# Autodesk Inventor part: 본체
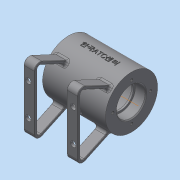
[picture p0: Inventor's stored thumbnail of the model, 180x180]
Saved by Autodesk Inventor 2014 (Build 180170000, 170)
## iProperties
Created: 2021-12
Part Number: 본체
Material: 일반
Document SubType Name: Modeling
Designer: dg
Density: 1 g/cm^3
Appearance: 기본값
Author: dg
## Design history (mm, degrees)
sketch "스케치1"
  geometry: L1 (0, 0)-(70, 0); L2 (0, 16)-(0, 29); L3 (0, 16)-(12, 16); L4 (12, 16)-(12, 14); L5 (12, 14)-(14, 14); L6 (14, 14)-(14, 21); L7 (14, 21)-(56, 21); L8 (56, 21)-(56, 14); L9 (56, 14)-(58, 14); L10 (58, 14)-(58, 16); L11 (58, 16)-(70, 16); L12 (70, 16)-(70, 29); L13 (0, 29)-(70, 29)
  constraints: 26 end point, 6 perpendicular, 5 parallel, 1 horizontal, 1 vertical alignment
  dimensions: "d0" = 70 distance of L1.start L1.end; "d1" = 32 diameter of L2.start L1; "d2" = 12 distance of L2.start L3.end; "d3" = 2 distance of L3.end L4.end; "d4" = 2 distance of L4.end L5.end; "d5" = 42 diameter of L6.end L1; "d6" = 42 distance of L6.end L7.end; "d7" = 2 distance of L8.end L9.end; "d8" = 2 distance of L9.end L10.end; "d9" = 12 distance of L10.end L11.end; "d10" = 32 diameter of L11 L1; "d11" = 58 diameter of L12.end L1; "d12" = 58 diameter of L2.end L1
revolve "회전1" sketch "스케치1" stored, may be unused: angle "d13" = 90 deg
node "작업축1"
fillet "모깎기1" dims "d14" = 3
fillet "모깎기2" dims "d15" = 0.3
node "작업 평면1"
sketch "스케치2"
  geometry: L1 (-55, 40)-(-55, -40); L2 (-55, 40)-(-17.993, 22.743); L3 (-55, -40)-(-17.993, -22.743); L4 (-20.438, -20.574)-(-52, -35.291); L5 (-52, -35.291)-(-52, 35.291); L6 (-52, 35.291)-(-20.438, 20.574); A1 r 29 centre (0, 0) between (-17.993, 22.743) and (-20.438, 20.574) reference; 1 further point
  constraints: 12 end point, 4 point on circle, 2 parallel, 1 vertical
  dimensions: "d17" = 55 distance from line of L1 point (0, 0); "d18" = 80 distance of L1.start L1.end; "d19" = 40 vertical distance of L1.start point (0, 0); "d20" = 65 deg angle of L1 L2; "d21" = 65 deg angle of L1 L3; "d22" = 3 distance between parallel lines of L3 L4; "d69" = 3 distance between parallel lines of L2 L6; "d70" = 3 distance between parallel lines of L5 L1
extrude "돌출1" join sketch "스케치2" stored distance "d25" = 60; taper "d26" = 0 deg
sketch "스케치4"
  geometry: C1 r 16 at (0, 0) reference; C2 r 29 at (0, 0) reference; A1 r 21 centre (0, 0) between (0, 21) and (21, 0); 2 further points
  constraints: 4 point on circle, 2 horizontal alignment, 2 vertical alignment, 1 centre point, 1 coincident
  dimensions: "d38" = 42 diameter of A1
hole "구멍1" sketch "스케치4" at (0, 21), (21, 0), (0, -21), (-21, 0) diameter "d39" = 3.242; stored, may be unused: countersink angle "d43" = 90 deg, drill point angle "d45" = 118 deg; dims "d40" = 8, "d41" = 4, "d42" = 2, "d44" = 10
node "작업 평면2"
sketch "스케치5"
  geometry: L1 (0, 29)-(0, -29) reference; C1 r 5 at (-35, 0); 2 further points
  constraints: 1 centre point, 1 horizontal alignment, 1 midpoint
  dimensions: "d47" = 35 distance from line of L1 C1.centre; "d48" = 10 diameter of C1
extrude "돌출4" join sketch "스케치5" stored distance "d49" = 36; taper "d50" = 0 deg
sketch "스케치6"
  geometry: C1 r 5 at (0, 0) reference; 2 further points
  constraints: 1 coincident
hole "구멍2" sketch "스케치6" at (0, 0) diameter "d51" = 5.188; stored, may be unused: countersink angle "d55" = 90 deg, drill point angle "d57" = 118 deg; dims "d52" = 6, "d53" = 4, "d54" = 2, "d56" = 8
fillet "모깎기6" dims "d58" = 1
chamfer "모따기1" distance "d59" = 1; stored, may be unused: second distance "d60" = 2, angle "d61" = 45 deg
sketch "스케치7"
  geometry: C1 r 5 at (0, 0) reference; C2 r 1.5 at (0, 0); 1 further point
  constraints: 1 centre point, 1 coincident
  dimensions: "d62" = 3 diameter of C2
extrude "돌출5" cut sketch "스케치7" stored distance "d63" = 36; taper "d64" = 0 deg
extrude "돌출6" cut sketch "스케치2" stored distance "d71" = 36; taper "d72" = 0 deg
fillet "모깎기8" dims "d73" = 6
fillet "모깎기9" dims "d74" = 3
sketch "스케치10"
  geometry: L1 (0, -61.164)-(0, 0) reference; L2 (60, 6)-(60, 0) reference; L3 (-5, -30.582)-(-8.484, -30.582); C1 r 3 at (5, -12.582); C2 r 3 at (55, -12.582); C3 r 3 at (5, -48.582); C4 r 3 at (55, -48.582); 1 further point
  constraints: 4 centre point, 2 end point, 2 symmetric about line, 1 horizontal alignment, 1 perpendicular, 2 other
  dimensions: "d75" = 18 vertical distance of L3.start C1.centre; "d76" = 5 distance from line of L1 C1.centre; "d77" = 6 diameter of C1; "d78" = 5 distance from line of C2.centre L2; "d79" = 6 diameter of C2
extrude "돌출7" cut sketch "스케치10" distance "d80" = 36; taper "d81" = 0 deg
fillet "모깎기10" dims "d82" = 0.5
fillet "모깎기11" dims "d83" = 3
node "작업 평면3"
sketch "스케치11"
  geometry: L1 (70, -29)-(70, 29) reference; L2 (0, -29)-(70, -29) reference; L3 (0, -29)-(0, 29) reference; 3 further points
  constraints: 1 horizontal alignment, 1 midpoint, 1 vertical alignment, 1 other
  dimensions: "d88" = 29 vertical distance of point (35, 0) L3.end (derived); "d89" = 35 distance from line of point (35, 0) L3 (derived)
feature "엠보싱1" sketch "스케치11" dims "d0" = 70, "d1" = 32, "d2" = 12, "d3" = 2, "d4" = 2, "d5" = 42, "d6" = 42, "d7" = 2, "d8" = 2, "d9" = 12, "d10" = 32, "d11" = 58, "d12" = 58, "d86" = 0.5, "d87" = 0
sketch "스케치12"
  geometry: L1 (0, 0)-(-30.07, -10.945); L2 (0, 0)-(-2.767, 0); L3 (-30.07, -10.945)-(-32.122, -5.306); L4 (-32.122, -5.306)-(-24.74, -2.619); L5 (-24.74, -2.619)-(-22.687, -8.258)
  constraints: 10 end point, 3 perpendicular, 1 horizontal, 1 point on line
  dimensions: "d90" = 32 distance of L1.start L1.end; "d91" = 20 deg angle of L1 L2; "d92" = 6 distance of L1.end L3.end
revolve "회전2" sketch "스케치12" stored, may be unused: angle "d93" = 90 deg
sketch "스케치13"
  geometry: C1 r 6 at (0, 0) reference; 2 further points
  constraints: 1 coincident
hole "구멍3" sketch "스케치13" at (0, 0) diameter "d94" = 5.188; stored, may be unused: countersink angle "d98" = 90 deg, drill point angle "d100" = 118 deg; dims "d95" = 13, "d96" = 4, "d97" = 2, "d99" = 15
fillet "모깎기12" dims "d101" = 1
node "솔리드1"
mirror "대칭1"
other parameters: "d16" = 35, "d23" = 24.474, "d46" = 32, "d84" = 29.5
